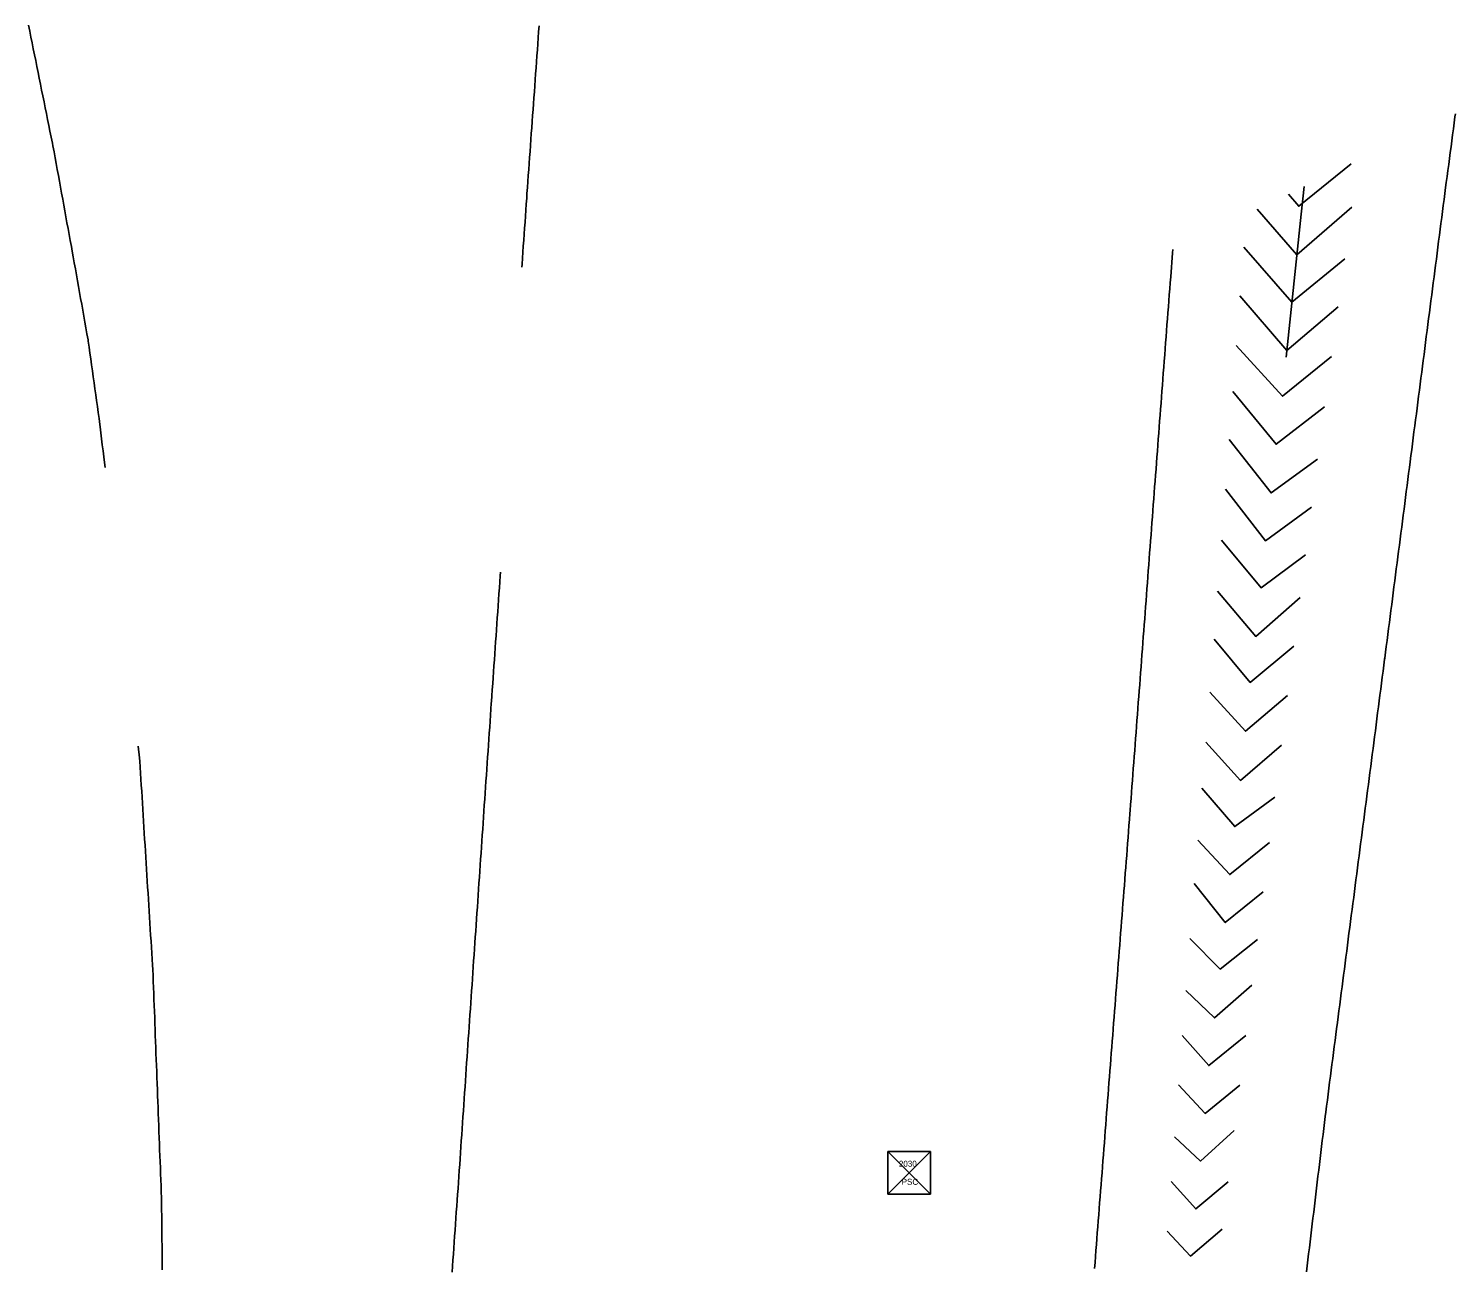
# Model space of a CAD drawing. Extents: x 205929 to 2357175, y -1785700 to 846739.
# Drawn here: x 2023492.7 to 2023730.1, y 811398.9 to 811605.1 of the extents above; entities that cross this region are included whole.
import ezdxf

# ---------------------------------------------------------------- set-up
doc = ezdxf.new("R2010")
doc.units = 0
for name, color, linetype in [('RD_HC_Survey', 7, 'Continuous'), ('RD_HC_txCode', 7, 'Continuous'), ('RD_Sketch1', 7, 'Continuous'), ('RD_SMD_Locator', 7, 'Continuous')]:
    doc.layers.add(name, color=color, linetype=linetype)

msp = doc.modelspace()

# ---------------------------------------------------------------- linework, layer by layer
at = {"layer": 'RD_HC_Survey'}
for p, q in [((2023635.69, 811418.18), (2023642.76, 811411.11)), ((2023642.76, 811418.18), (2023635.69, 811411.11)), ((2023642.76, 811418.18), (2023635.69, 811418.18)), ((2023635.69, 811418.18), (2023639.23, 811414.65)), ((2023639.23, 811414.65), (2023642.76, 811418.18)), ((2023639.23, 811414.65), (2023635.69, 811411.11)), ((2023642.76, 811411.11), (2023639.23, 811414.65)), ((2023635.69, 811411.11), (2023642.76, 811411.11))]:
    msp.add_line(p, q, dxfattribs=at)
msp.add_lwpolyline([(2023642.76, 811418.18), (2023635.69, 811418.18), (2023635.69, 811411.11), (2023642.76, 811411.11)], close=True, dxfattribs=at)
at = {"layer": 'RD_Sketch1'}
for points in [[(2023492.68, 811605.59), (2023492.87, 811604.61), (2023493.07, 811603.63), (2023493.27, 811602.65), (2023493.47, 811601.67), (2023493.67, 811600.69), (2023493.87, 811599.71), (2023494.07, 811598.73), (2023494.26, 811597.75), (2023494.46, 811596.77), (2023494.66, 811595.79), (2023494.86, 811594.81), (2023495.06, 811593.83), (2023495.26, 811592.85), (2023495.45, 811591.87), (2023495.65, 811590.89), (2023495.85, 811589.91), (2023496.05, 811588.93), (2023496.25, 811587.95), (2023496.45, 811586.97), (2023496.65, 811585.99), (2023496.74, 811585.53), (2023496.92, 811584.55), (2023497.1, 811583.56), (2023497.28, 811582.58), (2023497.46, 811581.6), (2023497.64, 811580.61), (2023497.82, 811579.63), (2023498, 811578.65), (2023498.18, 811577.66), (2023498.36, 811576.68), (2023498.54, 811575.69), (2023498.72, 811574.71), (2023498.9, 811573.73), (2023499.08, 811572.74), (2023499.27, 811571.76), (2023499.45, 811570.78), (2023499.63, 811569.79), (2023499.81, 811568.81), (2023499.95, 811568.03), (2023500.13, 811567.04), (2023500.3, 811566.06), (2023500.48, 811565.07), (2023500.65, 811564.09), (2023500.83, 811563.1), (2023501, 811562.12), (2023501.18, 811561.14), (2023501.35, 811560.15), (2023501.53, 811559.17), (2023501.7, 811558.18), (2023501.88, 811557.2), (2023502.05, 811556.21), (2023502.23, 811555.23), (2023502.4, 811554.25), (2023502.58, 811553.26), (2023502.62, 811553.04), (2023502.76, 811552.05), (2023502.89, 811551.06), (2023503.03, 811550.07), (2023503.17, 811549.08), (2023503.31, 811548.09), (2023503.45, 811547.1), (2023503.58, 811546.11), (2023503.72, 811545.12), (2023503.86, 811544.13), (2023504, 811543.15), (2023504.13, 811542.16), (2023504.27, 811541.17), (2023504.41, 811540.18), (2023504.55, 811539.19), (2023504.61, 811538.77), (2023504.72, 811537.78), (2023504.84, 811536.79), (2023504.96, 811535.79), (2023505.08, 811534.8), (2023505.19, 811533.81), (2023505.31, 811532.82), (2023505.41, 811532.01)], [(2023577.65, 811605.52), (2023577.57, 811604.52), (2023577.5, 811603.52), (2023577.43, 811602.53), (2023577.36, 811601.53), (2023577.29, 811600.53), (2023577.21, 811599.53), (2023577.14, 811598.54), (2023577.07, 811597.54), (2023577, 811596.54), (2023576.93, 811595.54), (2023576.86, 811594.55), (2023576.78, 811593.55), (2023576.71, 811592.55), (2023576.64, 811591.56), (2023576.57, 811590.56), (2023576.5, 811589.56), (2023576.42, 811588.56), (2023576.35, 811587.57), (2023576.28, 811586.57), (2023576.21, 811585.57), (2023576.14, 811584.58), (2023576.06, 811583.58), (2023575.99, 811582.58), (2023575.92, 811581.58), (2023575.85, 811580.59), (2023575.78, 811579.59), (2023575.71, 811578.59), (2023575.63, 811577.59), (2023575.58, 811576.81), (2023575.51, 811575.81), (2023575.44, 811574.82), (2023575.37, 811573.82), (2023575.3, 811572.82), (2023575.23, 811571.83), (2023575.16, 811570.83), (2023575.09, 811569.83), (2023575.02, 811568.83), (2023574.95, 811567.84), (2023574.88, 811566.84), (2023574.81, 811565.84), (2023574.77, 811565.34)], [(2023730.14, 811590.88), (2023730.06, 811590.34), (2023729.93, 811589.35), (2023729.8, 811588.36), (2023729.67, 811587.37), (2023729.54, 811586.38), (2023729.4, 811585.39), (2023729.27, 811584.4), (2023729.14, 811583.41), (2023729.01, 811582.42), (2023728.87, 811581.43), (2023728.74, 811580.44), (2023728.61, 811579.45), (2023728.5, 811578.59), (2023728.37, 811577.6), (2023728.24, 811576.61), (2023728.11, 811575.62), (2023727.98, 811574.62), (2023727.86, 811573.63), (2023727.73, 811572.64), (2023727.6, 811571.65), (2023727.47, 811570.66), (2023727.34, 811569.67), (2023727.21, 811568.68), (2023727.09, 811567.68), (2023726.96, 811566.69), (2023726.83, 811565.7), (2023726.7, 811564.71), (2023726.57, 811563.72), (2023726.45, 811562.73), (2023726.32, 811561.74), (2023726.19, 811560.74), (2023726.06, 811559.75), (2023725.93, 811558.76), (2023725.81, 811557.77), (2023725.68, 811556.78), (2023725.55, 811555.79), (2023725.42, 811554.8), (2023725.29, 811553.8), (2023725.16, 811552.81), (2023725.04, 811551.82), (2023724.91, 811550.83), (2023724.78, 811549.84), (2023724.65, 811548.85), (2023724.52, 811547.86), (2023724.4, 811546.86), (2023724.27, 811545.87), (2023724.14, 811544.88), (2023724.01, 811543.89), (2023723.88, 811542.9), (2023723.76, 811541.91), (2023723.63, 811540.92), (2023723.5, 811539.92), (2023723.37, 811538.93), (2023723.24, 811537.94), (2023723.11, 811536.95), (2023722.99, 811535.96), (2023722.86, 811534.97), (2023722.73, 811533.98), (2023722.6, 811532.98), (2023722.47, 811531.99), (2023722.35, 811531), (2023722.22, 811530.01), (2023722.09, 811529.02), (2023721.96, 811528.03), (2023721.83, 811527.04), (2023721.71, 811526.04), (2023721.58, 811525.05), (2023721.45, 811524.06), (2023721.32, 811523.07), (2023721.19, 811522.08), (2023721.06, 811521.09), (2023720.94, 811520.09), (2023720.81, 811519.1), (2023720.68, 811518.11), (2023720.55, 811517.12), (2023720.42, 811516.13), (2023720.3, 811515.14), (2023720.17, 811514.15), (2023720.04, 811513.15), (2023719.91, 811512.16), (2023719.78, 811511.17), (2023719.66, 811510.18), (2023719.53, 811509.19), (2023719.4, 811508.2), (2023719.27, 811507.21), (2023719.14, 811506.21), (2023719.01, 811505.22), (2023718.89, 811504.23), (2023718.76, 811503.24), (2023718.63, 811502.25), (2023718.5, 811501.26), (2023718.37, 811500.27), (2023718.35, 811500.1), (2023718.22, 811499.1), (2023718.09, 811498.11), (2023717.97, 811497.12), (2023717.84, 811496.13), (2023717.71, 811495.14), (2023717.58, 811494.15), (2023717.45, 811493.16), (2023717.32, 811492.17), (2023717.19, 811491.17), (2023717.06, 811490.18), (2023716.93, 811489.19), (2023716.81, 811488.2), (2023716.68, 811487.21), (2023716.55, 811486.22), (2023716.42, 811485.23), (2023716.29, 811484.23), (2023716.16, 811483.24), (2023716.03, 811482.25), (2023715.9, 811481.26), (2023715.77, 811480.27), (2023715.65, 811479.28), (2023715.52, 811478.29), (2023715.39, 811477.3), (2023715.26, 811476.3), (2023715.13, 811475.31), (2023715, 811474.32), (2023714.87, 811473.33), (2023714.74, 811472.34), (2023714.61, 811471.35), (2023714.49, 811470.36), (2023714.36, 811469.37), (2023714.23, 811468.37), (2023714.1, 811467.38), (2023713.97, 811466.39), (2023713.84, 811465.4), (2023713.71, 811464.41), (2023713.58, 811463.42), (2023713.45, 811462.43), (2023713.33, 811461.43), (2023713.2, 811460.44), (2023713.07, 811459.45), (2023712.94, 811458.46), (2023712.81, 811457.47), (2023712.68, 811456.48), (2023712.55, 811455.49), (2023712.42, 811454.5), (2023712.29, 811453.5), (2023712.17, 811452.51), (2023712.04, 811451.52), (2023711.91, 811450.53), (2023711.78, 811449.54), (2023711.65, 811448.55), (2023711.52, 811447.56), (2023711.39, 811446.57), (2023711.26, 811445.57), (2023711.14, 811444.58), (2023711.01, 811443.59), (2023710.88, 811442.6), (2023710.75, 811441.61), (2023710.62, 811440.62), (2023710.49, 811439.63), (2023710.36, 811438.63), (2023710.23, 811437.64), (2023710.1, 811436.65), (2023709.98, 811435.66), (2023709.85, 811434.67), (2023709.72, 811433.68), (2023709.59, 811432.69), (2023709.46, 811431.7), (2023709.33, 811430.7), (2023709.2, 811429.71), (2023709.07, 811428.72), (2023708.94, 811427.73), (2023708.82, 811426.74), (2023708.69, 811425.75), (2023708.56, 811424.76), (2023708.46, 811423.99), (2023708.34, 811423), (2023708.22, 811422.01), (2023708.1, 811421.01), (2023707.98, 811420.02), (2023707.86, 811419.03), (2023707.74, 811418.04), (2023707.62, 811417.04), (2023707.5, 811416.05), (2023707.38, 811415.06), (2023707.26, 811414.07), (2023707.14, 811413.08), (2023707.02, 811412.08), (2023706.9, 811411.09), (2023706.78, 811410.1), (2023706.67, 811409.11), (2023706.55, 811408.11), (2023706.43, 811407.12), (2023706.31, 811406.13), (2023706.19, 811405.14), (2023706.07, 811404.14), (2023705.95, 811403.15), (2023705.83, 811402.16), (2023705.71, 811401.17), (2023705.59, 811400.17), (2023705.47, 811399.18), (2023705.35, 811398.19)], [(2023702.35, 811577.52), (2023704.06, 811575.47), (2023712.77, 811582.54)], [(2023704.95, 811578.78), (2023704.45, 811574.16), (2023701.97, 811550.37)], [(2023697.14, 811575.01), (2023703.75, 811567.4), (2023712.9, 811575.31)], [(2023683.1, 811568.26), (2023683.06, 811567.71), (2023682.75, 811563.72), (2023682.67, 811562.73), (2023682.6, 811561.73), (2023682.52, 811560.73), (2023682.44, 811559.74), (2023682.36, 811558.74), (2023682.29, 811557.75), (2023682.21, 811556.75), (2023682.13, 811555.75), (2023682.06, 811554.76), (2023681.98, 811553.76), (2023681.9, 811552.76), (2023681.82, 811551.77), (2023681.75, 811550.77), (2023681.66, 811549.7), (2023681.59, 811548.71), (2023681.51, 811547.71), (2023681.44, 811546.71), (2023681.36, 811545.71), (2023681.29, 811544.72), (2023681.21, 811543.72), (2023681.14, 811542.72), (2023681.06, 811541.73), (2023680.99, 811540.73), (2023680.91, 811539.73), (2023680.84, 811538.74), (2023680.76, 811537.74), (2023680.68, 811536.74), (2023680.61, 811535.75), (2023680.53, 811534.75), (2023680.46, 811533.75), (2023680.38, 811532.76), (2023680.31, 811531.76), (2023680.23, 811530.76), (2023680.16, 811529.76), (2023680.08, 811528.77), (2023680.01, 811527.77), (2023679.93, 811526.77), (2023679.85, 811525.78), (2023679.78, 811524.78), (2023679.7, 811523.78), (2023679.63, 811522.79), (2023679.55, 811521.79), (2023679.48, 811520.79), (2023679.4, 811519.8), (2023679.33, 811518.8), (2023679.25, 811517.8), (2023679.18, 811516.81), (2023679.1, 811515.81), (2023679.02, 811514.81), (2023678.95, 811513.81), (2023678.87, 811512.82), (2023678.8, 811511.82), (2023678.72, 811510.82), (2023678.65, 811509.83), (2023678.57, 811508.83), (2023678.5, 811507.83), (2023678.42, 811506.84), (2023678.35, 811505.84), (2023678.27, 811504.84), (2023678.19, 811503.85), (2023678.12, 811502.85), (2023678.04, 811501.85), (2023677.97, 811500.86), (2023677.89, 811499.86), (2023677.82, 811498.86), (2023677.74, 811497.86), (2023677.67, 811496.87), (2023677.59, 811495.87), (2023677.52, 811494.87), (2023677.44, 811493.88), (2023677.36, 811492.88), (2023677.29, 811491.88), (2023677.21, 811490.89), (2023677.14, 811489.89), (2023677.06, 811488.89), (2023676.99, 811487.9), (2023676.91, 811486.9), (2023676.84, 811485.9), (2023676.76, 811484.9), (2023676.69, 811483.91), (2023676.61, 811482.91), (2023676.53, 811481.91), (2023676.46, 811480.92), (2023676.38, 811479.92), (2023676.31, 811478.92), (2023676.23, 811477.93), (2023676.16, 811476.93), (2023676.08, 811475.93), (2023676.01, 811474.94), (2023675.97, 811474.44), (2023675.89, 811473.44), (2023675.81, 811472.45), (2023675.74, 811471.45), (2023675.66, 811470.45), (2023675.58, 811469.46), (2023675.5, 811468.46), (2023675.43, 811467.46), (2023675.35, 811466.47), (2023675.27, 811465.47), (2023675.19, 811464.48), (2023675.12, 811463.48), (2023675.04, 811462.48), (2023674.96, 811461.49), (2023674.88, 811460.49), (2023674.81, 811459.49), (2023674.73, 811458.5), (2023674.65, 811457.5), (2023674.57, 811456.5), (2023674.5, 811455.51), (2023674.42, 811454.51), (2023674.34, 811453.51), (2023674.26, 811452.52), (2023674.19, 811451.52), (2023674.11, 811450.52), (2023674.03, 811449.53), (2023673.95, 811448.53), (2023673.88, 811447.53), (2023673.8, 811446.54), (2023673.72, 811445.54), (2023673.64, 811444.54), (2023673.57, 811443.55), (2023673.49, 811442.55), (2023673.41, 811441.55), (2023673.33, 811440.56), (2023673.26, 811439.56), (2023673.18, 811438.56), (2023673.1, 811437.57), (2023673.02, 811436.57), (2023672.95, 811435.57), (2023672.87, 811434.58), (2023672.79, 811433.58), (2023672.71, 811432.59), (2023672.64, 811431.59), (2023672.56, 811430.59), (2023672.48, 811429.6), (2023672.4, 811428.6), (2023672.33, 811427.6), (2023672.25, 811426.61), (2023672.17, 811425.61), (2023672.09, 811424.61), (2023672.02, 811423.62), (2023671.94, 811422.62), (2023671.86, 811421.62), (2023671.78, 811420.63), (2023671.71, 811419.63), (2023671.63, 811418.63), (2023671.55, 811417.64), (2023671.47, 811416.64), (2023671.4, 811415.64), (2023671.32, 811414.65), (2023671.24, 811413.65), (2023671.16, 811412.65), (2023671.09, 811411.66), (2023671.01, 811410.66), (2023670.93, 811409.66), (2023670.85, 811408.67), (2023670.78, 811407.67), (2023670.7, 811406.67), (2023670.62, 811405.68), (2023670.54, 811404.68), (2023670.47, 811403.68), (2023670.39, 811402.69), (2023670.31, 811401.69), (2023670.23, 811400.7), (2023670.16, 811399.7), (2023670.08, 811398.7)], [(2023694.9, 811568.65), (2023702.92, 811559.51), (2023711.72, 811566.71)], [(2023694.28, 811560.55), (2023702.09, 811551.49), (2023710.64, 811558.77)], [(2023693.66, 811552.31), (2023701.37, 811543.86), (2023709.51, 811550.5)], [(2023693.08, 811544.66), (2023700.3, 811535.88), (2023708.36, 811542.13)], [(2023692.47, 811536.66), (2023699.45, 811527.79), (2023707.19, 811533.42)], [(2023691.85, 811528.43), (2023698.55, 811519.79), (2023706.17, 811525.39)], [(2023691.2, 811519.94), (2023697.79, 811512.01), (2023705.17, 811517.46)], [(2023571.22, 811514.6), (2023571.18, 811513.99), (2023571.11, 811512.99), (2023571.04, 811511.99), (2023570.97, 811511), (2023570.9, 811510), (2023570.83, 811509), (2023570.76, 811508), (2023570.69, 811507.01), (2023570.62, 811506.01), (2023570.55, 811505.01), (2023570.48, 811504.01), (2023570.41, 811503.02), (2023570.34, 811502.02), (2023570.27, 811501.02), (2023570.2, 811500.03), (2023570.13, 811499.03), (2023570.06, 811498.03), (2023569.99, 811497.03), (2023569.92, 811496.04), (2023569.85, 811495.04), (2023569.78, 811494.04), (2023569.71, 811493.05), (2023569.69, 811492.77), (2023569.62, 811491.78), (2023569.56, 811490.78), (2023569.49, 811489.78), (2023569.42, 811488.79), (2023569.35, 811487.79), (2023569.28, 811486.79), (2023569.21, 811485.79), (2023569.15, 811484.8), (2023569.08, 811483.8), (2023569.01, 811482.8), (2023568.94, 811481.81), (2023568.87, 811480.81), (2023568.8, 811479.81), (2023568.74, 811478.81), (2023568.67, 811477.82), (2023568.6, 811476.82), (2023568.53, 811475.82), (2023568.46, 811474.82), (2023568.39, 811473.83), (2023568.33, 811472.83), (2023568.26, 811471.83), (2023568.19, 811470.84), (2023568.12, 811469.84), (2023568.05, 811468.84), (2023567.98, 811467.84), (2023567.92, 811466.85), (2023567.85, 811465.85), (2023567.78, 811464.85), (2023567.71, 811463.86), (2023567.64, 811462.86), (2023567.57, 811461.86), (2023567.51, 811460.86), (2023567.44, 811459.87), (2023567.37, 811458.87), (2023567.3, 811457.87), (2023567.23, 811456.88), (2023567.16, 811455.88), (2023567.09, 811454.88), (2023567.03, 811453.88), (2023566.96, 811452.89), (2023566.89, 811451.89), (2023566.82, 811450.89), (2023566.75, 811449.9), (2023566.68, 811448.9), (2023566.62, 811447.9), (2023566.55, 811446.9), (2023566.48, 811445.91), (2023566.41, 811444.91), (2023566.34, 811443.91), (2023566.27, 811442.92), (2023566.21, 811441.92), (2023566.14, 811440.92), (2023566.07, 811439.92), (2023566, 811438.93), (2023565.93, 811437.93), (2023565.86, 811436.93), (2023565.8, 811435.93), (2023565.73, 811434.94), (2023565.66, 811433.94), (2023565.59, 811432.94), (2023565.52, 811431.95), (2023565.45, 811430.95), (2023565.39, 811429.95), (2023565.32, 811428.95), (2023565.25, 811427.96), (2023565.18, 811426.96), (2023565.11, 811425.96), (2023565.04, 811424.97), (2023564.98, 811423.97), (2023564.91, 811422.97), (2023564.84, 811421.97), (2023564.77, 811420.98), (2023564.7, 811419.98), (2023564.63, 811418.98), (2023564.57, 811417.99), (2023564.5, 811416.99), (2023564.43, 811416.05), (2023564.36, 811415.05), (2023564.29, 811414.05), (2023564.22, 811413.06), (2023564.15, 811412.06), (2023564.08, 811411.06), (2023564.01, 811410.07), (2023563.94, 811409.07), (2023563.87, 811408.07), (2023563.8, 811407.07), (2023563.73, 811406.08), (2023563.66, 811405.08), (2023563.59, 811404.08), (2023563.52, 811403.09), (2023563.45, 811402.09), (2023563.38, 811401.09), (2023563.31, 811400.09), (2023563.24, 811399.1), (2023563.17, 811398.1)], [(2023690.56, 811511.42), (2023696.91, 811503.91), (2023704.27, 811510.37)], [(2023689.96, 811503.47), (2023695.99, 811496.26), (2023703.24, 811502.29)], [(2023689.25, 811494.6), (2023695.21, 811488.12), (2023702.2, 811494.07)], [(2023688.58, 811486.31), (2023694.34, 811479.95), (2023701.17, 811485.82)], [(2023510.9, 811485.66), (2023510.96, 811485.16), (2023511.07, 811484.17), (2023511.19, 811483.15), (2023511.26, 811482.15), (2023511.32, 811481.15), (2023511.38, 811480.15), (2023511.44, 811479.16), (2023511.51, 811478.16), (2023511.57, 811477.16), (2023511.63, 811476.16), (2023511.69, 811475.16), (2023511.75, 811474.17), (2023511.82, 811473.17), (2023511.88, 811472.17), (2023511.94, 811471.17), (2023512, 811470.17), (2023512.07, 811469.18), (2023512.13, 811468.18), (2023512.19, 811467.18), (2023512.25, 811466.18), (2023512.32, 811465.18), (2023512.38, 811464.19), (2023512.44, 811463.19), (2023512.5, 811462.19), (2023512.57, 811461.19), (2023512.63, 811460.19), (2023512.69, 811459.2), (2023512.75, 811458.2), (2023512.81, 811457.2), (2023512.88, 811456.2), (2023512.94, 811455.2), (2023513, 811454.21), (2023513.06, 811453.21), (2023513.13, 811452.21), (2023513.19, 811451.21), (2023513.25, 811450.21), (2023513.31, 811449.22), (2023513.36, 811448.47), (2023513.4, 811447.47), (2023513.44, 811446.47), (2023513.47, 811445.47), (2023513.51, 811444.47), (2023513.55, 811443.47), (2023513.59, 811442.47), (2023513.63, 811441.47), (2023513.67, 811440.47), (2023513.7, 811439.47), (2023513.74, 811438.47), (2023513.78, 811437.48), (2023513.82, 811436.48), (2023513.86, 811435.48), (2023513.89, 811434.48), (2023513.93, 811433.48), (2023513.97, 811432.48), (2023514.01, 811431.48), (2023514.05, 811430.48), (2023514.08, 811429.48), (2023514.12, 811428.48), (2023514.16, 811427.48), (2023514.2, 811426.49), (2023514.24, 811425.49), (2023514.27, 811424.49), (2023514.31, 811423.49), (2023514.35, 811422.49), (2023514.39, 811421.49), (2023514.43, 811420.49), (2023514.47, 811419.49), (2023514.5, 811418.49), (2023514.54, 811417.49), (2023514.58, 811416.49), (2023514.62, 811415.5), (2023514.66, 811414.5), (2023514.69, 811413.5), (2023514.73, 811412.5), (2023514.77, 811411.5), (2023514.81, 811410.49), (2023514.82, 811409.49), (2023514.83, 811408.49), (2023514.84, 811407.49), (2023514.85, 811406.5), (2023514.86, 811405.5), (2023514.87, 811404.5), (2023514.88, 811403.5), (2023514.89, 811402.5), (2023514.91, 811401.5), (2023514.92, 811400.5), (2023514.93, 811399.5), (2023514.94, 811398.5)], [(2023687.96, 811478.67), (2023693.42, 811472.26), (2023700.1, 811477.17)], [(2023687.26, 811469.99), (2023692.57, 811464.26), (2023699.17, 811469.62)], [(2023686.68, 811462.81), (2023691.83, 811456.27), (2023698.15, 811461.4)], [(2023685.93, 811453.61), (2023690.99, 811448.54), (2023697.17, 811453.48)], [(2023685.26, 811444.99), (2023690.06, 811440.41), (2023696.25, 811445.89)], [(2023684.68, 811437.47), (2023689.08, 811432.49), (2023695.23, 811437.47)], [(2023684.06, 811429.29), (2023688.48, 811424.54), (2023694.24, 811429.25)], [(2023683.39, 811420.62), (2023687.7, 811416.61), (2023693.33, 811421.66)], [(2023682.83, 811413.2), (2023686.93, 811408.64), (2023692.3, 811413.14)], [(2023682.19, 811404.92), (2023686.06, 811400.78), (2023691.33, 811405.26)]]:
    msp.add_lwpolyline(points, dxfattribs=at)
at = {"layer": 'RD_SMD_Locator'}
msp.add_circle((2023639.23, 811414.65), 0.001, dxfattribs=at)

# ---------------------------------------------------------------- texts
at = {"layer": 'RD_HC_txCode'}
for s, p in [('2030', (2023637.52, 811415.65)), ('PSC', (2023637.98, 811412.65))]:
    msp.add_text(s, height=1, dxfattribs=at).set_placement(p)

doc.saveas('drawing.dxf')
